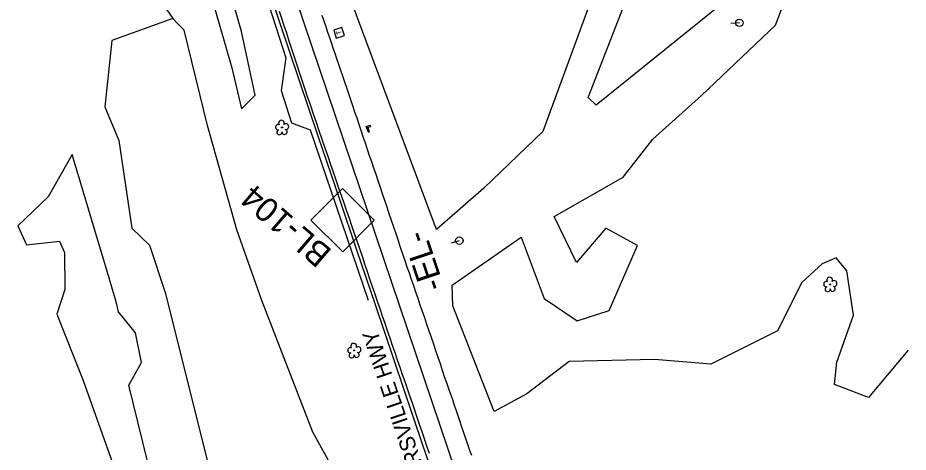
# Model space of a CAD drawing. Extents: x 478596 to 483012, y 490885 to 495165.
# Drawn here: x 480923 to 481513, y 492235 to 492523 of the extents above; entities that cross this region are included whole.
import ezdxf

# ---------------------------------------------------------------- set-up
doc = ezdxf.new("R2010")
doc.units = 0
for name, color, linetype in [('CTL Secondary Horizontal and Vertical CELL', 7, 'Continuous'), ('CTL Secondary Horizontal and Vertical Text', 7, 'Continuous'), ('Exist Guardrail', 7, 'Continuous'), ('Exist Horizontal Alignment', 7, 'Continuous'), ('Exist Horizontal Alignment Direction Label', 7, 'Continuous'), ('Exist Roads EOP', 7, 'Continuous'), ('Exist Roads EOP Text', 7, 'Continuous'), ('Exist Structure Major Bridge WW', 7, 'Continuous'), ('Exist Structure Minor Head and End Wall', 7, 'Continuous'), ('Exist Utilities Other Pole CELL', 7, 'Continuous'), ('Exist Utilities Power Pole CELL', 7, 'Continuous'), ('Exist Utilities Telephone Pedestal CELL', 7, 'Continuous'), ('Exist Vegetation Hedge Row', 7, 'Continuous'), ('Exist Vegetation Tree CELL', 7, 'Continuous'), ('Exist Vegetation Woods Line', 7, 'Continuous')]:
    doc.layers.add(name, color=color, linetype=linetype)

msp = doc.modelspace()

# ---------------------------------------------------------------- linework, layer by layer
at = {"layer": 'CTL Secondary Horizontal and Vertical CELL'}
msp.add_line((481138.1, 492388.81), (481138.1, 492388.81), dxfattribs=at)
msp.add_lwpolyline([(481117.24, 492388.88), (481138.2, 492409.84), (481159.2, 492388.84), (481138.24, 492367.88)], close=True, dxfattribs=at)
at = {"layer": 'Exist Guardrail'}
for points in [[(481159.92, 492332.85), (481147.67, 492369.02), (481136.31, 492402.63), (481122.19, 492443.94), (481109.37, 492481.77), (481096.99, 492518.51), (481082.03, 492563.66), (481066.9, 492608.24), (481049.63, 492658.22), (481035.22, 492698.61), (481023.2, 492728.97), (481010.06, 492758.78), (480999.42, 492781.5)], [(481268.81, 492000.43), (481250.05, 492063.45), (481229.61, 492126.12), (481209.51, 492187.09), (481191.12, 492240.55), (481159.92, 492332.85)]]:
    msp.add_lwpolyline(points, dxfattribs=at)
at = {"layer": 'Exist Horizontal Alignment'}
msp.add_line((481314.86, 491922.25), (481071.89, 492639.91), dxfattribs=at)
at = {"layer": 'Exist Roads EOP'}
for points in [[(481195.66, 492234.39), (481194.06, 492239.14), (481192.46, 492243.9), (481190.85, 492248.67), (481189.24, 492253.43), (481187.63, 492258.2), (481186.03, 492262.96), (481184.42, 492267.7), (481182.81, 492272.4), (481181.21, 492277.08), (481179.59, 492281.77), (481177.96, 492286.51), (481176.31, 492291.28), (481174.63, 492296.1), (481172.95, 492300.94), (481171.29, 492305.78), (481169.63, 492310.62), (481167.98, 492315.46), (481166.34, 492320.31), (481164.68, 492325.18), (481163.02, 492330.06), (481161.34, 492334.96), (481159.66, 492339.87), (481157.99, 492344.79), (481156.32, 492349.72), (481154.65, 492354.67), (481152.97, 492359.65), (481151.27, 492364.7), (481149.54, 492369.81), (481147.78, 492374.99), (481146.03, 492380.13), (481144.32, 492385.14), (481142.65, 492390.02), (481141.02, 492394.77), (481139.38, 492399.52), (481137.7, 492404.43), (481135.96, 492409.48), (481134.18, 492414.68), (481132.35, 492420.01), (481130.48, 492425.44), (481128.58, 492430.99), (481126.63, 492436.65), (481124.68, 492442.34), (481122.75, 492447.97), (481120.84, 492453.54), (481118.95, 492459.05), (481117.09, 492464.52), (481115.25, 492469.96), (481113.44, 492475.37), (481111.65, 492480.75), (481109.88, 492486.12), (481108.11, 492491.49), (481106.36, 492496.86), (481104.61, 492502.23), (481102.88, 492507.51), (481101.2, 492512.63), (481099.57, 492517.57), (481097.98, 492522.36), (481096.44, 492527)], [(481124.48, 492524.61), (481125.76, 492520.81), (481127.01, 492517.06), (481128.24, 492513.43), (481129.43, 492509.9), (481130.58, 492506.48), (481131.74, 492503.07), (481132.95, 492499.53), (481134.19, 492495.89), (481135.47, 492492.14), (481136.78, 492488.31), (481138.1, 492484.46), (481139.42, 492480.57), (481140.75, 492476.65), (481142.09, 492472.71), (481143.43, 492468.74), (481144.78, 492464.73), (481146.14, 492460.7), (481147.51, 492456.64), (481148.88, 492452.54), (481150.27, 492448.42), (481151.67, 492444.27), (481153.07, 492440.1), (481154.47, 492435.94), (481155.87, 492431.79), (481157.27, 492427.64), (481158.68, 492423.48), (481160.11, 492419.28), (481161.55, 492415.03), (481163.01, 492410.74), (481164.48, 492406.42), (481165.95, 492402.08), (481167.42, 492397.71), (481168.9, 492393.31), (481170.38, 492388.89), (481171.88, 492384.43), (481173.39, 492379.92), (481174.91, 492375.39), (481176.42, 492370.88), (481177.91, 492366.48), (481179.37, 492362.19), (481180.79, 492358), (481182.21, 492353.86), (481183.63, 492349.7), (481185.06, 492345.52), (481186.5, 492341.32), (481187.95, 492337.1), (481189.4, 492332.86), (481190.87, 492328.59), (481192.35, 492324.3), (481193.83, 492319.98), (481195.32, 492315.64), (481196.81, 492311.26), (481198.31, 492306.86), (481199.8, 492302.47), (481201.27, 492298.12), (481202.73, 492293.81), (481204.17, 492289.55), (481205.58, 492285.38), (481206.96, 492281.34), (481208.31, 492277.43), (481209.62, 492273.66), (481210.91, 492269.99), (481212.15, 492266.39), (481213.36, 492262.87), (481214.54, 492259.42), (481215.68, 492256.04), (481216.81, 492252.72), (481217.93, 492249.48), (481219.02, 492246.29), (481220.11, 492243.11), (481221.22, 492239.86), (481222.35, 492236.54), (481223.49, 492233.16)]]:
    msp.add_lwpolyline(points, dxfattribs=at)
at = {"layer": 'Exist Structure Major Bridge WW'}
for points in [[(481155.3, 492447.06), (481153.81, 492450.95), (481156.45, 492451.72)], [(481156.08, 492447.36), (481154.91, 492450.4), (481156.68, 492450.92)]]:
    msp.add_lwpolyline(points, dxfattribs=at)
at = {"layer": 'Exist Structure Minor Head and End Wall'}
for p, q in [((481156.45, 492451.72), (481156.68, 492450.92)), ((481155.3, 492447.06), (481156.08, 492447.36))]:
    msp.add_line(p, q, dxfattribs=at)
at = {"layer": 'Exist Utilities Other Pole CELL'}
msp.add_circle((481215.5, 492375.27), 2.46, dxfattribs=at)
at = {"layer": 'Exist Utilities Power Pole CELL'}
for p, q in [((481401.09, 492519.61), (481395.48, 492519.11)), ((481401.09, 492519.61), (481401.09, 492519.61)), ((481215.5, 492375.27), (481210.09, 492373.73)), ((481215.5, 492375.27), (481215.5, 492375.27))]:
    msp.add_line(p, q, dxfattribs=at)
for centre in [(481401.09, 492519.61), (481215.5, 492375.27)]:
    msp.add_circle(centre, 2.45, dxfattribs=at)
at = {"layer": 'Exist Utilities Telephone Pedestal CELL'}
msp.add_line((481135.81, 492512.81), (481135.81, 492512.81), dxfattribs=at)
msp.add_lwpolyline([(481139.33, 492511.09), (481137.62, 492516.41), (481132.29, 492514.69), (481134.01, 492509.37), (481139.33, 492511.09)], dxfattribs=at)
at = {"layer": 'Exist Vegetation Hedge Row'}
for points in [[(481045.91, 492555.24), (481064.72, 492489.67), (481071.1, 492462.65), (481080.2, 492471.74), (481071.23, 492513.93), (481054.53, 492571.95)], [(481078.23, 492565.63), (481100.49, 492496.39), (481097.57, 492474.75), (481104.41, 492453.27), (481116.79, 492448.69), (481155.16, 492335.93)], [(481084.64, 492335.71), (481068.08, 492382.46), (481048.59, 492451.56), (481033.29, 492514.67), (481028.86, 492519.16), (481025.69, 492522.53)], [(481218.82, 492043.64), (481210.36, 492053.43), (481199.59, 492070.01), (481194.83, 492082.01), (481182.3, 492117.17), (481166.69, 492152.71), (481152.18, 492170.83), (481143.63, 492202.94), (481118.35, 492248.52), (481084.64, 492335.71)]]:
    msp.add_lwpolyline(points, dxfattribs=at)
at = {"layer": 'Exist Vegetation Tree CELL'}
for p, q in [((481098.02, 492450.28), (481098.02, 492450.28)), ((481461.28, 492346.3), (481461.28, 492346.3)), ((481145.87, 492302.53), (481145.87, 492302.53))]:
    msp.add_line(p, q, dxfattribs=at)
for centre in [(481098.02, 492450.28), (481461.28, 492346.3), (481145.87, 492302.53)]:
    msp.add_circle(centre, 0.326, dxfattribs=at)
for centre, radius, start, end in [((481095.42, 492450.44), 1.73, 62.66361, 279.3457), ((481097.64, 492453.16), 1.86, 330.16508, 219.71335), ((481100.57, 492450.87), 1.9, 257.1011, 134.19993), ((481096.32, 492447.16), 1.69, 111.56708, 6.23104), ((481099.7, 492447.38), 1.7, 181.28216, 74.55999), ((481460.89, 492349.18), 1.86, 330.16508, 219.71335), ((481458.67, 492346.46), 1.73, 62.66361, 279.3457), ((481459.57, 492343.18), 1.69, 111.56708, 6.23104), ((481462.95, 492343.4), 1.7, 181.28216, 74.55999), ((481463.83, 492346.89), 1.9, 257.1011, 134.19993), ((481143.27, 492302.68), 1.73, 62.66361, 279.3457), ((481145.49, 492305.4), 1.86, 330.16508, 219.71335), ((481148.42, 492303.12), 1.9, 257.1011, 134.19993), ((481144.17, 492299.41), 1.69, 111.56708, 6.23104), ((481147.55, 492299.63), 1.7, 181.28216, 74.55999)]:
    msp.add_arc(centre, radius, start, end, dxfattribs=at)
at = {"layer": 'Exist Vegetation Woods Line'}
for points in [[(480974.69, 492591.01), (480973.9, 492587.17), (480968.85, 492568.82), (480971.6, 492529.52), (480993.18, 492532.19), (481017.27, 492534.67), (481025.69, 492522.53), (480985.34, 492507.97), (480980.63, 492463.84), (480989.86, 492441.63), (480998.61, 492383.63), (481010.32, 492372.34), (481020.94, 492340.18)], [(481398.38, 492539.51), (481306.3, 492465.09), (481300.85, 492470.08), (481340.6, 492572.41)], [(481308.35, 492550.11), (481270.95, 492447.58), (481231.76, 492409.96), (481200.38, 492382.62), (481135.69, 492556.19)], [(481210.75, 492345.9), (481256.6, 492377.57), (481271.73, 492336.93), (481293.65, 492322.2), (481314.89, 492328.93), (481333.59, 492372.11), (481312.55, 492383.66), (481293.23, 492360.74), (481278.44, 492391.18), (481324.02, 492417.37), (481343.8, 492442.46), (481376.08, 492471.51), (481424.98, 492517.94), (481432.45, 492537.91)], [(480988.16, 492334.8), (480982.32, 492354.29), (480959, 492432.33), (480942.99, 492404.34), (480922.98, 492385.15), (480928.69, 492372.51), (480950.59, 492374.9), (480953.93, 492367.48), (480954.07, 492342.92), (480948.88, 492326.59)], [(481472.3, 492355.24), (481465.31, 492363.84), (481455.83, 492359.89), (481442.49, 492347.47)], [(481512.93, 492302.75), (481486.56, 492271.47), (481464.08, 492280.09), (481465.55, 492294.89), (481476.59, 492325.82), (481472.3, 492355.24)], [(481442.49, 492347.47), (481426.34, 492315.57), (481382.23, 492293.45), (481344.77, 492296.57), (481288.23, 492295.2), (481260.32, 492273.84), (481238.71, 492262.16), (481211.15, 492332.07), (481210.75, 492345.9)], [(481020.94, 492340.18), (481055.15, 492203.11), (481077.11, 492116.92), (481051.27, 492107.76)], [(481051.27, 492107.76), (481042.69, 492127.11), (481030.16, 492134.67), (481022.98, 492140.69), (481020.65, 492146.68), (481033.17, 492156.31), (481020.7, 492209.94), (481009, 492229.32), (480996.51, 492279.58), (481004.83, 492294.59), (481000.97, 492314.17), (480989.61, 492328.07), (480988.16, 492334.8)], [(480948.88, 492326.59), (480966.39, 492282.65), (481008.69, 492163.7), (480990.8, 492145.59)]]:
    msp.add_lwpolyline(points, dxfattribs=at)

# ---------------------------------------------------------------- texts
at = {"layer": 'CTL Secondary Horizontal and Vertical Text'}
msp.add_text('BL-104', height=16, rotation=139.37956, dxfattribs=at).set_placement((481131.91, 492368.57))
at = {"layer": 'Exist Horizontal Alignment Direction Label'}
msp.add_text('-EL-', height=16, rotation=108.52386, dxfattribs=at).set_placement((481205.67, 492344.74))
at = {"layer": 'Exist Roads EOP Text'}
msp.add_text('US19/129 BLAIRSVILLE HWY', height=10.4, rotation=108.63096, dxfattribs=at).set_placement((481221.44, 492137.55))
at = {"layer": 'Exist Utilities Telephone Pedestal CELL'}
msp.add_text('T', height=3.42, rotation=107.89192, dxfattribs=at).set_placement((481137.79, 492512.26))

doc.saveas('drawing.dxf')
